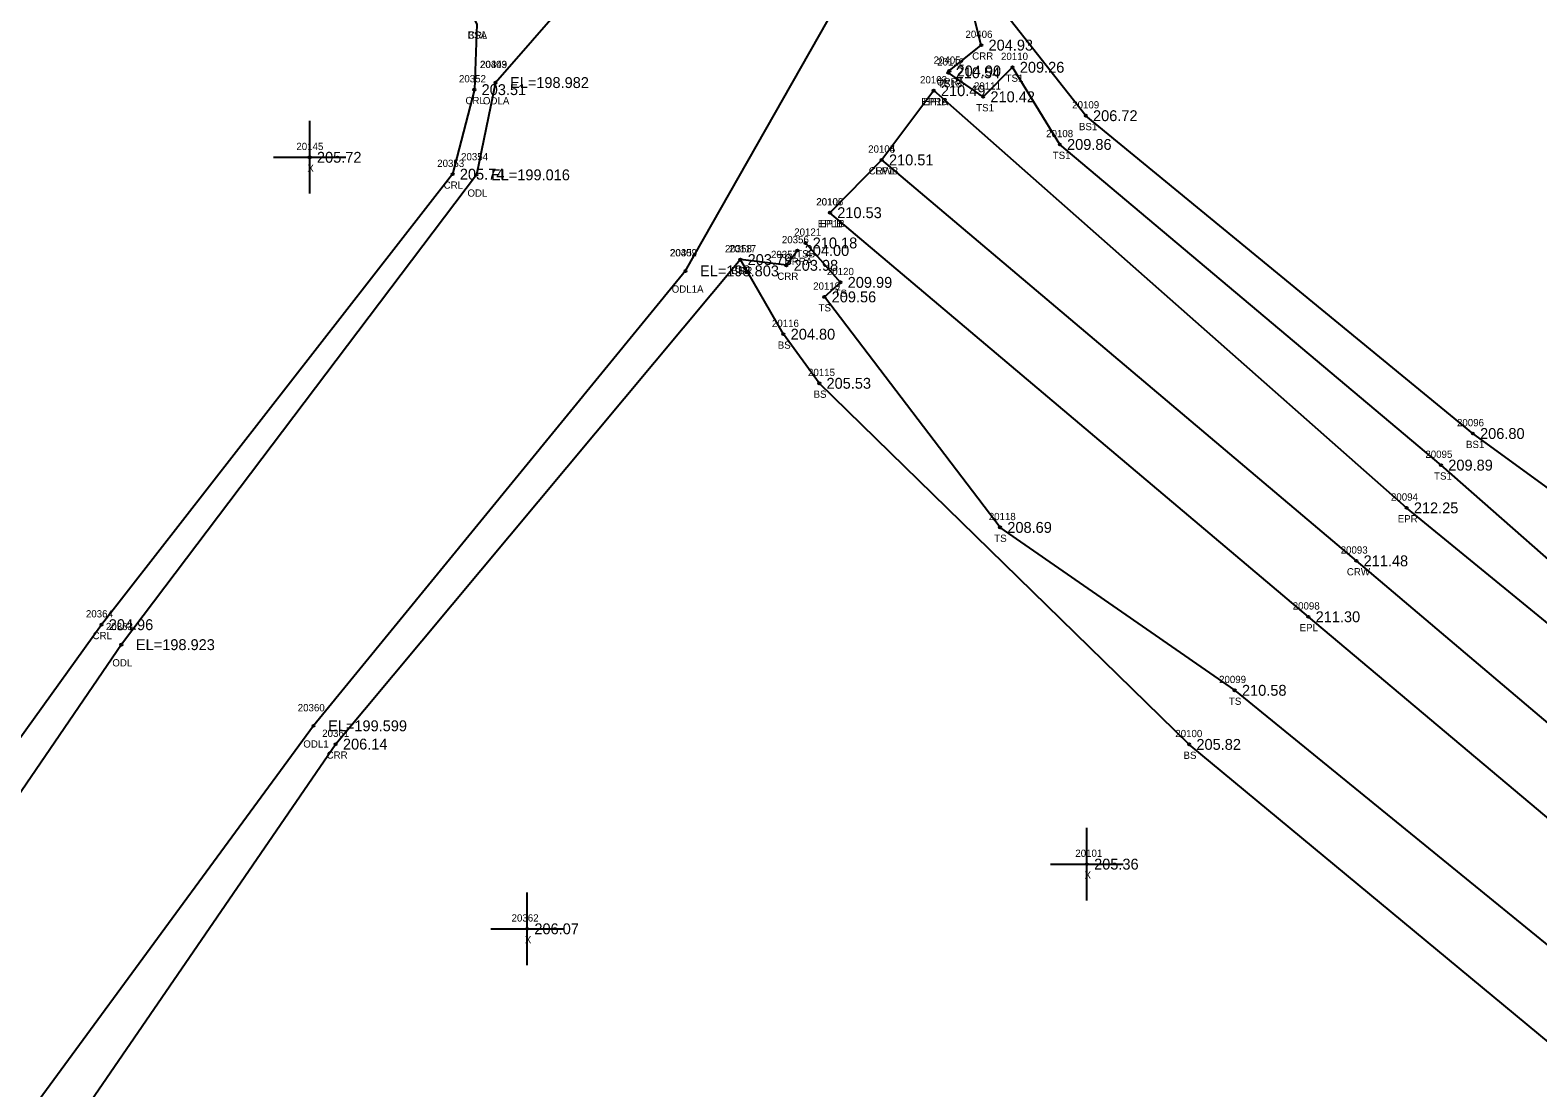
# Model space of a CAD drawing. Extents: x 2260230 to 2261304, y 1064626 to 1065587.
# Drawn here: x 2260708.4 to 2260916.2, y 1064937.7 to 1065083.4 of the extents above; entities that cross this region are included whole.
import ezdxf

# ---------------------------------------------------------------- set-up
doc = ezdxf.new("R2010")
doc.units = 0
for name, color, linetype in [('RD_DTM_BkLn1', 7, 'Continuous'), ('RD_DTM_BkLn2', 7, 'Continuous'), ('RD_DTM_BkLn_txCode', 7, 'Continuous'), ('RD_EX_H2O', 7, 'Continuous'), ('RD_EX_H2O_txCode', 7, 'Continuous'), ('RD_EX_Misc', 7, 'Continuous'), ('RD_EX_Misc_txCode', 7, 'Continuous'), ('RD_EX_Road', 7, 'Continuous'), ('RD_EX_Road_txCode', 7, 'Continuous'), ('RD_EX_TX_H2O_ELEV', 7, 'Continuous'), ('RD_EX_TX_Misc_ELEV', 7, 'Continuous'), ('RD_EX_TX_Road_ELEV', 7, 'Continuous'), ('RD_HC_Survey_ELEV', 7, 'Continuous'), ('RD_HC_Survey_txCode', 7, 'Continuous'), ('RD_SMD_Locator', 7, 'Continuous')]:
    doc.layers.add(name, color=color, linetype=linetype)

msp = doc.modelspace()

# ---------------------------------------------------------------- linework, layer by layer
at = {"layer": 'RD_DTM_BkLn1'}
msp.add_lwpolyline([(2261119.39, 1064818.57), (2261039.33, 1064885.27), (2260966.22, 1064946.78), (2260891.14, 1065010.3), (2260825.73, 1065065.53)], dxfattribs=at)
at = {"layer": 'RD_DTM_BkLn2'}
for points in [[(2260956, 1065026.37), (2260943.74, 1065012.58), (2260930.09, 1065011.21), (2260907.19, 1065027.84), (2260853.85, 1065071.62), (2260836.25, 1065093.94)], [(2260956.75, 1065024.52), (2260944.16, 1065006.49), (2260936.81, 1065001.24), (2260926.77, 1065002.44), (2260902.81, 1065023.49), (2260850.27, 1065067.66), (2260843.76, 1065078.29), (2260839.71, 1065074.22), (2260834.92, 1065077.53)], [(2261107.5, 1064803.56), (2261026.54, 1064870.98), (2260948.4, 1064932.24), (2260874.38, 1064992.47), (2260842.04, 1065014.91), (2260817.83, 1065046.66), (2260820.04, 1065048.66), (2260815.22, 1065054.09)], [(2261101.75, 1064796.17), (2261015.65, 1064858.96), (2260944.13, 1064922.06), (2260868.1, 1064985.02), (2260817.12, 1065034.76), (2260812.18, 1065041.52), (2260806.25, 1065051.8)]]:
    msp.add_lwpolyline(points, dxfattribs=at)
at = {"layer": 'RD_EX_H2O'}
for points in [[(2260772.5, 1065076.18), (2260808.2, 1065117.04), (2260848.54, 1065142.46), (2260881.52, 1065170.81), (2260885.55, 1065179.82), (2260940.26, 1065230.7), (2260962.59, 1065234.94), (2260997.55, 1065261.89), (2261039.02, 1065251.85), (2261039.02, 1065251.85), (2261052.94, 1065229.55), (2261043.13, 1065204.67), (2261054.65, 1065194.09), (2261077.36, 1065181.43), (2261181.44, 1065185.78), (2261286.2, 1065209.29)], [(2260798.69, 1065050.24), (2260824.47, 1065095.61), (2260899.49, 1065151.99), (2260934.71, 1065184.11), (2260972.92, 1065212.25), (2260990.72, 1065208.66), (2261010.85, 1065196.45), (2261038.36, 1065172.55), (2261071.49, 1065162.95), (2261185.1, 1065163.45), (2261291.17, 1065187.86)], [(2260835.04, 1065077.78), (2260839.45, 1065081.34), (2260836.25, 1065093.94), (2260905.11, 1065142.54), (2260939.15, 1065178.33), (2260943.42, 1065185.77), (2260976.49, 1065206.39), (2260992.26, 1065206.09), (2261009.06, 1065194.12), (2261027.03, 1065166.48), (2261074.3, 1065153.35), (2261181.18, 1065157.65), (2261291.85, 1065184.94)], [(2260766.96, 1065089.79), (2260769.94, 1065084.22), (2260769.59, 1065075.21), (2260766.59, 1065063.56), (2260718.2, 1065001.51), (2260666.03, 1064928.94), (2260617.31, 1064851.47), (2260573.34, 1064761.94), (2260536.11, 1064718.88), (2260488.15, 1064682.39)], [(2260772.5, 1065076.18), (2260769.88, 1065063.47), (2260720.95, 1064998.76), (2260670.41, 1064924.84), (2260623.49, 1064846.38), (2260577.39, 1064759), (2260539.32, 1064716.5), (2260492, 1064679.21)], [(2260814.11, 1065053.05), (2260812.59, 1065051.01), (2260806.25, 1065051.8), (2260750.48, 1064985.06), (2260697.06, 1064907.27), (2260648.8, 1064826.07), (2260606.38, 1064743.85), (2260584.89, 1064714.82), (2260586.34, 1064702.25), (2260547.45, 1064661.75), (2260541.67, 1064664.24), (2260523.34, 1064649.3)], [(2260798.69, 1065050.24), (2260747.43, 1064987.58), (2260691.08, 1064910.92), (2260641.97, 1064830.24), (2260601.17, 1064746.82), (2260578.03, 1064718.93), (2260582.86, 1064704.22), (2260538.26, 1064666.33), (2260517.69, 1064657.12)]]:
    msp.add_lwpolyline(points, dxfattribs=at)
at = {"layer": 'RD_EX_Misc'}
for p, q in [((2260746.9, 1065060.89), (2260746.9, 1065070.89)), ((2260741.9, 1065065.89), (2260751.9, 1065065.89)), ((2260854, 1064963.53), (2260854, 1064973.53)), ((2260849, 1064968.53), (2260859, 1064968.53)), ((2260776.86, 1064954.62), (2260776.86, 1064964.62)), ((2260771.86, 1064959.62), (2260781.86, 1064959.62))]:
    msp.add_line(p, q, dxfattribs=at)
at = {"layer": 'RD_EX_Road'}
for points in [[(2260832.89, 1065075.07), (2260825.73, 1065065.53), (2260818.6, 1065058.26)], [(2261124.91, 1064827.37), (2261072.16, 1064871.6), (2261053.72, 1064886.47), (2261045.58, 1064893.1), (2260972.89, 1064954.76), (2260940.74, 1064982.39), (2260933.33, 1064988.76), (2260898.06, 1065017.6), (2260832.89, 1065075.07)], [(2261112.68, 1064810.86), (2261032.95, 1064877.72), (2260956.01, 1064942.53), (2260884.53, 1065002.6), (2260818.6, 1065058.26)]]:
    msp.add_lwpolyline(points, dxfattribs=at)
at = {"layer": 'RD_SMD_Locator'}
for centre in [(2260839.45, 1065081.34), (2260843.76, 1065078.29), (2260772.5, 1065076.18), (2260772.5, 1065076.18), (2260834.92, 1065077.53), (2260835.04, 1065077.78), (2260769.59, 1065075.21), (2260832.89, 1065075.07), (2260832.89, 1065075.07), (2260839.71, 1065074.22), (2260853.85, 1065071.62), (2260746.9, 1065065.89), (2260850.27, 1065067.66), (2260825.73, 1065065.53), (2260825.73, 1065065.53), (2260766.59, 1065063.56), (2260769.88, 1065063.47), (2260818.6, 1065058.26), (2260818.6, 1065058.26), (2260815.22, 1065054.09), (2260806.25, 1065051.8), (2260806.25, 1065051.8), (2260814.11, 1065053.05), (2260798.69, 1065050.24), (2260798.69, 1065050.24), (2260812.59, 1065051.01), (2260820.04, 1065048.66), (2260817.83, 1065046.66), (2260812.18, 1065041.52), (2260817.12, 1065034.76), (2260907.19, 1065027.84), (2260902.81, 1065023.49), (2260898.06, 1065017.6), (2260842.04, 1065014.91), (2260891.14, 1065010.3), (2260718.2, 1065001.51), (2260884.53, 1065002.6), (2260720.95, 1064998.76), (2260874.38, 1064992.47), (2260747.43, 1064987.58), (2260750.48, 1064985.06), (2260868.1, 1064985.02), (2260854, 1064968.53), (2260776.86, 1064959.62)]:
    msp.add_circle(centre, 0.15, dxfattribs=at)

# ---------------------------------------------------------------- texts
at = {"layer": 'RD_DTM_BkLn_txCode'}
for s, p in [('BSA', (2260768.67, 1065082.22)), ('20112', (2260833.37, 1065078.53)), ('20110', (2260842.17, 1065079.29)), ('TS1B', (2260833.48, 1065075.53)), ('20111', (2260838.44, 1065075.22)), ('TS1', (2260842.8, 1065076.29)), ('TS1', (2260838.75, 1065072.22)), ('20109', (2260851.98, 1065072.62)), ('BS1', (2260852.91, 1065069.62)), ('20108', (2260848.39, 1065068.66)), ('TS1', (2260849.3, 1065065.66)), ('20121', (2260813.67, 1065055.09)), ('20117', (2260804.7, 1065052.8)), ('TSB', (2260813.95, 1065052.09)), ('BSB', (2260805, 1065049.8)), ('20120', (2260818.17, 1065049.66)), ('20119', (2260816.28, 1065047.66)), ('TS', (2260819.24, 1065046.66)), ('TS', (2260817.03, 1065044.66)), ('20116', (2260810.6, 1065042.52)), ('BS', (2260811.4, 1065039.52)), ('20115', (2260815.57, 1065035.76)), ('BS', (2260816.34, 1065032.76)), ('20096', (2260905.01, 1065028.84)), ('BS1', (2260906.25, 1065025.84)), ('20095', (2260900.65, 1065024.49)), ('TS1', (2260901.85, 1065021.49)), ('20118', (2260840.48, 1065015.91)), ('TS', (2260841.24, 1065012.91)), ('20099', (2260872.22, 1064993.47)), ('TS', (2260873.58, 1064990.47)), ('20100', (2260866.19, 1064986.02)), ('BS', (2260867.32, 1064983.02))]:
    msp.add_text(s, height=1, dxfattribs=at).set_placement(p)
at = {"layer": 'RD_EX_H2O_txCode'}
for s, p in [('CRL', (2260768.71, 1065082.22)), ('20406', (2260837.27, 1065082.34)), ('20403', (2260770.35, 1065078.18)), ('20349', (2260770.39, 1065078.18)), ('20405', (2260832.88, 1065078.78)), ('CRR', (2260838.2, 1065079.34)), ('20352', (2260767.47, 1065076.21)), ('CRRA', (2260833.3, 1065075.78)), ('CRL', (2260768.36, 1065073.21)), ('ODLA', (2260770.77, 1065073.18)), ('ODLA', (2260770.77, 1065073.18)), ('20354', (2260767.76, 1065065.47)), ('20353', (2260764.47, 1065064.56)), ('CRL', (2260765.36, 1065061.56)), ('ODL', (2260768.64, 1065060.47)), ('20358', (2260804.13, 1065052.8)), ('20356', (2260811.97, 1065054.05)), ('20402', (2260796.53, 1065052.24)), ('20359', (2260796.57, 1065052.24)), ('20357', (2260810.47, 1065052.01)), ('CRRA', (2260812.37, 1065051.05)), ('CRR', (2260805, 1065049.8)), ('CRR', (2260811.34, 1065049.01)), ('ODL1A', (2260796.79, 1065047.24)), ('ODL1A', (2260796.79, 1065047.24)), ('20364', (2260716.06, 1065002.51)), ('20363', (2260718.81, 1065000.76)), ('CRL', (2260716.97, 1064999.51)), ('ODL', (2260719.7, 1064995.76)), ('20360', (2260745.25, 1064989.58)), ('20361', (2260748.62, 1064986.06)), ('ODL1', (2260746.02, 1064984.58)), ('CRR', (2260749.23, 1064983.06))]:
    msp.add_text(s, height=1, dxfattribs=at).set_placement(p)
at = {"layer": 'RD_EX_Misc_txCode'}
for s, p in [('20145', (2260745.06, 1065066.89)), ('X', (2260746.58, 1065063.89)), ('20101', (2260852.41, 1064969.53)), ('X', (2260853.68, 1064966.53)), ('20362', (2260774.72, 1064960.62)), ('X', (2260776.55, 1064957.62))]:
    msp.add_text(s, height=1, dxfattribs=at).set_placement(p)
at = {"layer": 'RD_EX_Road_txCode'}
for s, p in [('20102', (2260831.01, 1065076.07)), ('20103', (2260831.01, 1065076.07)), ('EPRB', (2260831.19, 1065073.07)), ('EP1A', (2260831.48, 1065073.07)), ('20104', (2260823.86, 1065066.53)), ('EP1', (2260824.81, 1065063.53)), ('20106', (2260816.7, 1065059.26)), ('20107', (2260816.73, 1065059.26)), ('EPLB', (2260816.92, 1065056.26)), ('EP1B', (2260817.21, 1065056.26)), ('20094', (2260895.91, 1065018.6)), ('EPR', (2260896.84, 1065015.6)), ('20098', (2260882.37, 1065003.6)), ('EPL', (2260883.32, 1065000.6))]:
    msp.add_text(s, height=1, dxfattribs=at).set_placement(p)
at = {"layer": 'RD_EX_TX_H2O_ELEV'}
for s, p in [('204.93', (2260840.45, 1065080.59)), ('204.90', (2260836.04, 1065077.03)), ('EL=198.982', (2260774.5, 1065075.43)), ('EL=198.982', (2260774.5, 1065075.43)), ('203.51', (2260770.59, 1065074.46)), ('205.74', (2260767.59, 1065062.81)), ('EL=199.016', (2260771.88, 1065062.72)), ('204.00', (2260815.11, 1065052.3)), ('203.79', (2260807.25, 1065051.05)), ('203.98', (2260813.59, 1065050.26)), ('EL=198.803', (2260800.69, 1065049.49)), ('EL=198.803', (2260800.69, 1065049.49)), ('204.96', (2260719.2, 1065000.76)), ('EL=198.923', (2260722.95, 1064998.01)), ('EL=199.599', (2260749.43, 1064986.83)), ('206.14', (2260751.48, 1064984.31))]:
    msp.add_text(s, height=1.5, dxfattribs=at).set_placement(p)
at = {"layer": 'RD_EX_TX_Misc_ELEV'}
for s, p in [('209.26', (2260844.76, 1065077.54)), ('210.54', (2260835.92, 1065076.78)), ('210.42', (2260840.71, 1065073.47)), ('206.72', (2260854.85, 1065070.87)), ('209.86', (2260851.27, 1065066.91)), ('205.72', (2260747.9, 1065065.14)), ('210.18', (2260816.22, 1065053.34)), ('203.79', (2260807.25, 1065051.05)), ('209.99', (2260821.04, 1065047.91)), ('209.56', (2260818.83, 1065045.91)), ('204.80', (2260813.18, 1065040.77)), ('205.53', (2260818.12, 1065034.01)), ('206.80', (2260908.19, 1065027.09)), ('209.89', (2260903.81, 1065022.74)), ('208.69', (2260843.04, 1065014.16)), ('210.58', (2260875.38, 1064991.72)), ('205.82', (2260869.1, 1064984.27)), ('205.36', (2260855, 1064967.78)), ('206.07', (2260777.86, 1064958.87))]:
    msp.add_text(s, height=1.5, dxfattribs=at).set_placement(p)
at = {"layer": 'RD_EX_TX_Road_ELEV'}
for s, p in [('210.49', (2260833.89, 1065074.32)), ('210.49', (2260833.89, 1065074.32)), ('210.51', (2260826.73, 1065064.78)), ('210.53', (2260819.6, 1065057.51)), ('210.53', (2260819.6, 1065057.51)), ('212.25', (2260899.06, 1065016.85)), ('211.30', (2260885.53, 1065001.85))]:
    msp.add_text(s, height=1.5, dxfattribs=at).set_placement(p)
at = {"layer": 'RD_HC_Survey_ELEV'}
for s, p in [('210.51', (2260826.73, 1065064.78)), ('211.48', (2260892.14, 1065009.55))]:
    msp.add_text(s, height=1.5, dxfattribs=at).set_placement(p)
at = {"layer": 'RD_HC_Survey_txCode'}
for s, p in [('20105', (2260823.86, 1065066.53)), ('CRWB', (2260823.94, 1065063.53)), ('20093', (2260888.98, 1065011.3)), ('CRW', (2260889.83, 1065008.3))]:
    msp.add_text(s, height=1, dxfattribs=at).set_placement(p)

doc.saveas('drawing.dxf')
